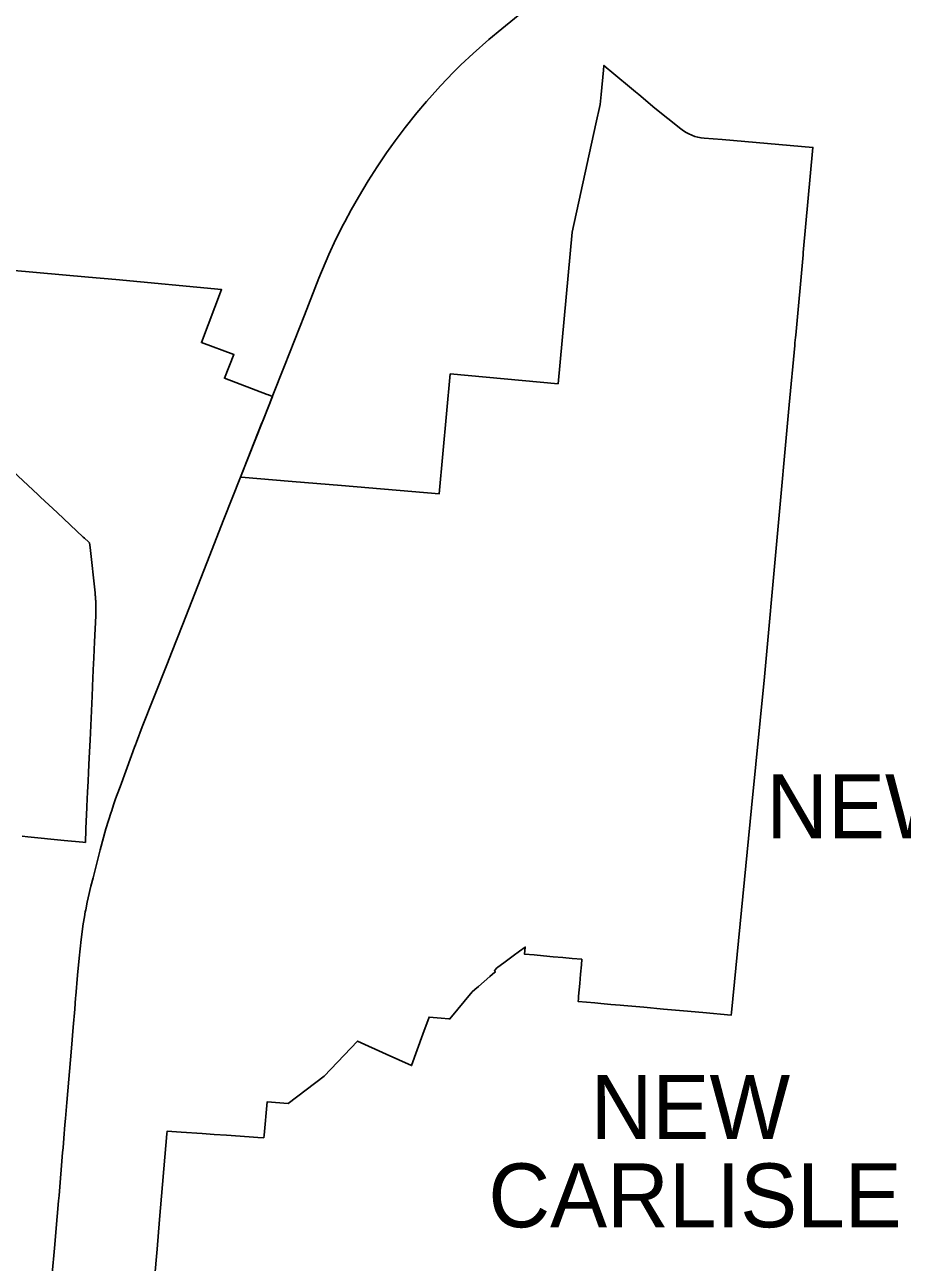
# Model space of a CAD drawing. Extents: x 0 to 34, y 0 to 22.
# Drawn here: x 6.0685 to 6.1789, y 16.1987 to 16.3544 of the extents above; entities that cross this region are included whole.
import ezdxf

# ---------------------------------------------------------------- set-up
doc = ezdxf.new("R2010")
doc.units = 0
for name, color, linetype in [('GM_X_Corporation', 7, 'Continuous'), ('GM_X_Corporation_Text', 7, 'Continuous'), ('GM_X_State_Route', 7, 'Continuous')]:
    doc.layers.add(name, color=color, linetype=linetype)

msp = doc.modelspace()

# ---------------------------------------------------------------- linework, layer by layer
at = {"layer": 'GM_X_Corporation'}
for points in [[(6.05409, 16.32468), (6.07653, 16.32266), (6.07997, 16.32235), (6.09327, 16.3211), (6.09073, 16.31443), (6.09482, 16.31292), (6.09363, 16.30993), (6.09902, 16.3079), (6.09917, 16.30785), (6.09966, 16.30766), (6.09849, 16.30467), (6.09826, 16.3041), (6.09566, 16.29751), (6.09622, 16.29746), (6.09966, 16.29717), (6.10216, 16.29696), (6.10836, 16.29643), (6.12063, 16.29539), (6.12203, 16.31048), (6.13559, 16.30924), (6.13737, 16.32831), (6.14035, 16.34195), (6.14088, 16.34438), (6.141, 16.34565), (6.14129, 16.34871), (6.14134, 16.34929), (6.14188, 16.34884), (6.14211, 16.34866), (6.14533, 16.34595), (6.14572, 16.34562), (6.14775, 16.34391), (6.15102, 16.34133), (6.15134, 16.34108), (6.15168, 16.34086), (6.15203, 16.34067), (6.15239, 16.3405), (6.15277, 16.34037), (6.15315, 16.34026), (6.15356, 16.34018), (6.15397, 16.34014), (6.15622, 16.33999), (6.16763, 16.33897), (6.16642, 16.32577), (6.16639, 16.32545), (6.16546, 16.31534), (6.16544, 16.31507), (6.16537, 16.31438), (6.16534, 16.31406), (6.16466, 16.30659), (6.16152, 16.27237), (6.15991, 16.2559), (6.15738, 16.23013), (6.15735, 16.22981), (6.15377, 16.23013), (6.15137, 16.23035), (6.14883, 16.23058), (6.14635, 16.2308), (6.14384, 16.23103), (6.14339, 16.23107), (6.1422, 16.23117), (6.14098, 16.23128), (6.14021, 16.23135), (6.1381, 16.23154), (6.13813, 16.23186), (6.13815, 16.23202), (6.13816, 16.23218), (6.1383, 16.23381), (6.13841, 16.23496), (6.13851, 16.23612), (6.13857, 16.23684), (6.13737, 16.23695), (6.13617, 16.23706), (6.13497, 16.23716), (6.13377, 16.23727), (6.13257, 16.23738), (6.13137, 16.23748), (6.13145, 16.23838), (6.13074, 16.23786), (6.12995, 16.23728), (6.12894, 16.23653), (6.12784, 16.23572), (6.12758, 16.23539), (6.12771, 16.23525), (6.12765, 16.2352), (6.127, 16.23469), (6.12557, 16.23343), (6.12511, 16.23302), (6.12478, 16.23273), (6.12199, 16.22934), (6.12185, 16.22935), (6.12088, 16.22944), (6.11989, 16.22953), (6.11937, 16.22957), (6.11859, 16.22742), (6.11716, 16.22346), (6.11397, 16.22491), (6.11038, 16.22654), (6.10618, 16.22213), (6.10166, 16.21868), (6.09899, 16.21889), (6.09861, 16.2147), (6.09858, 16.21438), (6.09783, 16.21443), (6.0973, 16.21447), (6.09672, 16.21451), (6.09391, 16.2147), (6.09232, 16.21481), (6.09084, 16.21491), (6.08819, 16.21509), (6.08641, 16.21521), (6.08638, 16.21489), (6.08547, 16.2041), (6.08516, 16.20038), (6.08484, 16.19664)], [(6.06821, 16.25231), (6.06891, 16.25224), (6.07349, 16.2518), (6.07582, 16.25158), (6.07615, 16.25155), (6.0762, 16.25316), (6.07621, 16.25329), (6.07633, 16.25594), (6.07634, 16.25605), (6.07643, 16.2579), (6.07649, 16.25921), (6.07654, 16.26036), (6.07663, 16.26218), (6.07673, 16.26442), (6.07698, 16.26992), (6.07708, 16.27227), (6.07712, 16.27313), (6.07713, 16.27325), (6.0772, 16.27478), (6.0772, 16.27478), (6.0773, 16.27679), (6.07745, 16.28004), (6.07746, 16.28041), (6.07746, 16.28043), (6.07746, 16.28044), (6.07746, 16.28046), (6.07746, 16.28048), (6.07746, 16.28049), (6.07747, 16.28051), (6.07747, 16.28052), (6.07747, 16.28054), (6.07747, 16.28055), (6.07747, 16.28057), (6.07747, 16.28059), (6.07747, 16.2806), (6.07747, 16.28062), (6.07747, 16.28063), (6.07747, 16.28065), (6.07747, 16.28066), (6.07747, 16.28068), (6.07747, 16.2807), (6.07747, 16.28071), (6.07747, 16.28073), (6.07747, 16.28074), (6.07747, 16.28076), (6.07747, 16.28077), (6.07747, 16.28079), (6.07747, 16.28081), (6.07747, 16.28082), (6.07747, 16.28084), (6.07747, 16.28085), (6.07747, 16.28087), (6.07747, 16.28089), (6.07747, 16.2809), (6.07747, 16.28092), (6.07747, 16.28093), (6.07747, 16.28095), (6.07747, 16.28096), (6.07747, 16.28098), (6.07747, 16.281), (6.07747, 16.28101), (6.07747, 16.28103), (6.07747, 16.28104), (6.07747, 16.28106), (6.07747, 16.28107), (6.07747, 16.28109), (6.07747, 16.28111), (6.07747, 16.28112), (6.07747, 16.28114), (6.07747, 16.28115), (6.07747, 16.28117), (6.07747, 16.28118), (6.07747, 16.2812), (6.07747, 16.28122), (6.07747, 16.28123), (6.07746, 16.28125), (6.07746, 16.28126), (6.07746, 16.28128), (6.07746, 16.28129), (6.07746, 16.28131), (6.07746, 16.28133), (6.07746, 16.28134), (6.07746, 16.28136), (6.07746, 16.28137), (6.07746, 16.28139), (6.07746, 16.2814), (6.07746, 16.28142), (6.07746, 16.28144), (6.07746, 16.28145), (6.07746, 16.28147), (6.07746, 16.28148), (6.07746, 16.2815), (6.07746, 16.28151), (6.07746, 16.28153), (6.07746, 16.28155), (6.07746, 16.28156), (6.07746, 16.28158), (6.07746, 16.28159), (6.07745, 16.28161), (6.07745, 16.28162), (6.07745, 16.28164), (6.07745, 16.28166), (6.07745, 16.28167), (6.07745, 16.28169), (6.07745, 16.2817), (6.07745, 16.28172), (6.07745, 16.28173), (6.07745, 16.28175), (6.07745, 16.28177), (6.07745, 16.28178), (6.07745, 16.2818), (6.07745, 16.28181), (6.07744, 16.28183), (6.07744, 16.28184), (6.07744, 16.28186), (6.07744, 16.28188), (6.07744, 16.28189), (6.07744, 16.28191), (6.07744, 16.28192), (6.07744, 16.28194), (6.07744, 16.28195), (6.07744, 16.28197), (6.07744, 16.28199), (6.07744, 16.282), (6.07743, 16.28202), (6.07743, 16.28203), (6.07743, 16.28205), (6.07743, 16.28206), (6.07743, 16.28208), (6.07743, 16.2821), (6.07743, 16.28211), (6.07743, 16.28213), (6.07743, 16.28214), (6.07743, 16.28216), (6.07742, 16.28217), (6.07742, 16.28219), (6.07742, 16.28221), (6.07742, 16.28222), (6.07742, 16.28224), (6.07742, 16.28225), (6.07742, 16.28227), (6.07742, 16.28228), (6.07742, 16.2823), (6.07741, 16.28232), (6.07741, 16.28233), (6.07741, 16.28235), (6.07741, 16.28236), (6.07741, 16.28238), (6.07741, 16.28239), (6.07741, 16.28241), (6.07741, 16.28243), (6.0774, 16.28244), (6.0774, 16.28246), (6.0774, 16.28247), (6.0774, 16.28249), (6.0774, 16.2825), (6.0774, 16.28252), (6.0774, 16.28254), (6.0774, 16.28255), (6.07739, 16.28257), (6.07739, 16.28258), (6.07739, 16.2826), (6.07739, 16.28261), (6.07739, 16.28263), (6.07739, 16.28264), (6.07739, 16.28266), (6.07738, 16.28268), (6.07738, 16.28269), (6.07738, 16.28271), (6.07738, 16.28272), (6.07738, 16.28274), (6.07738, 16.28275), (6.07738, 16.28277), (6.07737, 16.28279), (6.07737, 16.2828), (6.07737, 16.28282), (6.07737, 16.28283), (6.07737, 16.28284), (6.07737, 16.28285), (6.07737, 16.28286), (6.07736, 16.28288), (6.07736, 16.28289), (6.07736, 16.2829), (6.07736, 16.28291), (6.07736, 16.28292), (6.07736, 16.28294), (6.07736, 16.28295), (6.07674, 16.28865), (6.07668, 16.28921), (6.07652, 16.28936), (6.07603, 16.28982), (6.07588, 16.28995), (6.07258, 16.29304), (6.0705, 16.29498), (6.07034, 16.29513), (6.07015, 16.29531), (6.06706, 16.2982)]]:
    msp.add_lwpolyline(points, dxfattribs=at)
at = {"layer": 'GM_X_State_Route'}
for points in [[(6.10877, 16.32963), (6.10957, 16.33111), (6.11048, 16.33272), (6.11169, 16.33477), (6.11282, 16.33655), (6.114, 16.3383), (6.11509, 16.3398), (6.11636, 16.34148), (6.11784, 16.34334), (6.11903, 16.34475), (6.12048, 16.34636), (6.1208, 16.34671), (6.12242, 16.34845), (6.12336, 16.34938), (6.12491, 16.3508), (6.12689, 16.35255), (6.12851, 16.35391), (6.13215, 16.35688)], [(6.09965, 16.30761), (6.10118, 16.31148), (6.10368, 16.31786), (6.10552, 16.32252), (6.10675, 16.32549), (6.10765, 16.32745), (6.1086, 16.32933), (6.10877, 16.32963)], [(6.09566, 16.29749), (6.09934, 16.30682), (6.09965, 16.30761)], [(6.08839, 16.279), (6.09142, 16.28673), (6.09357, 16.2922), (6.09566, 16.29749)], [(6.08256, 16.26414), (6.0833, 16.26609), (6.08474, 16.26977), (6.08646, 16.27411), (6.08698, 16.27541), (6.08839, 16.279)], [(6.07995, 16.25701), (6.08015, 16.25756), (6.08051, 16.25855), (6.0814, 16.26097), (6.08233, 16.26354), (6.08244, 16.26381), (6.08256, 16.26414)], [(6.07941, 16.25545), (6.07973, 16.25638), (6.07995, 16.25701)], [(6.07619, 16.24308), (6.07638, 16.24403), (6.0765, 16.24458), (6.07684, 16.24602), (6.07711, 16.2471), (6.07801, 16.25062), (6.07873, 16.25323), (6.07939, 16.25536), (6.07941, 16.25545)], [(6.07192, 16.19685), (6.07231, 16.20096), (6.07243, 16.20252), (6.07277, 16.20646), (6.07283, 16.2071), (6.07329, 16.21251), (6.07334, 16.21312), (6.07344, 16.21432), (6.07358, 16.21601), (6.07365, 16.21682), (6.07383, 16.21882), (6.07441, 16.22565), (6.07461, 16.22828), (6.0748, 16.23055), (6.07492, 16.23197), (6.07494, 16.23226), (6.07516, 16.23486), (6.07535, 16.23698), (6.07562, 16.23931), (6.07588, 16.24129), (6.07602, 16.24218), (6.07614, 16.24281), (6.07616, 16.24295), (6.07619, 16.24308)]]:
    msp.add_lwpolyline(points, dxfattribs=at)

# ---------------------------------------------------------------- texts
at = {"layer": 'GM_X_Corporation_Text'}
for s, p in [('NEW CARLISLE', (6.16175, 16.25207)), ('NEW', (6.13969, 16.21424)), ('CARLISLE', (6.12682, 16.20312))]:
    msp.add_text(s, height=0.008037, rotation=0, dxfattribs=at).set_placement(p)

doc.saveas('drawing.dxf')
